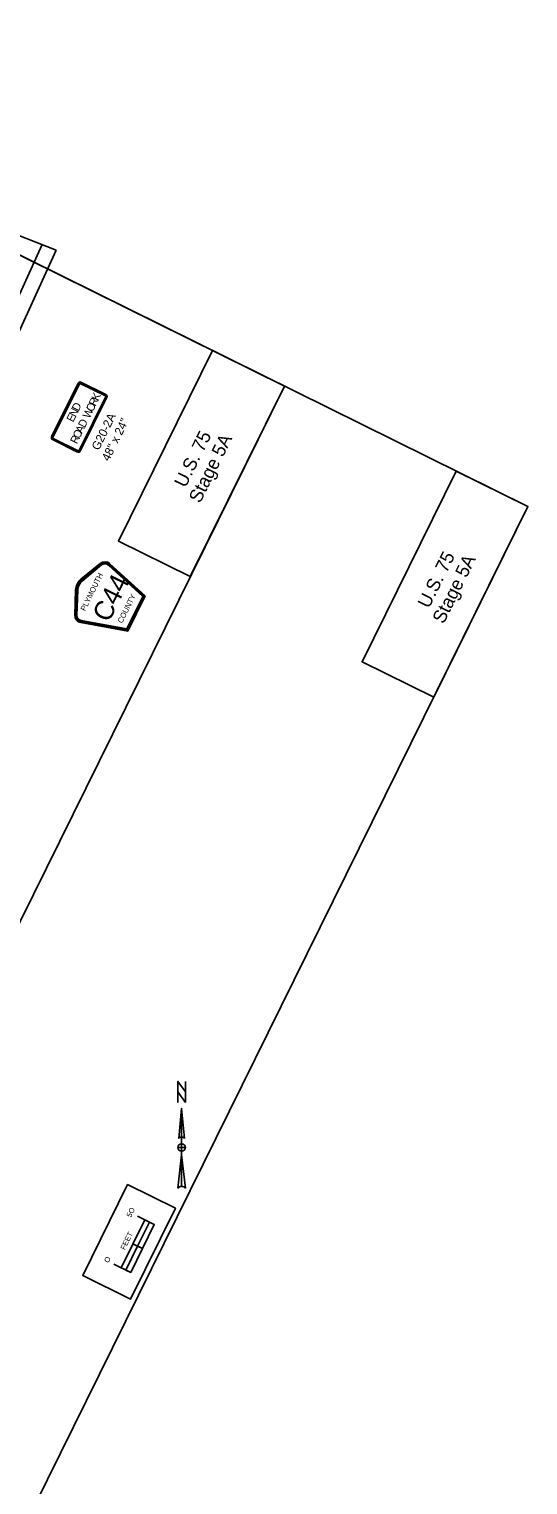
# Model space of a CAD drawing. Extents: x 14104283 to 14129344, y 8637090 to 8673339.
# Drawn here: x 14120414 to 14120882, y 8670301 to 8671666 of the extents above; entities that cross this region are included whole.
import ezdxf

# ---------------------------------------------------------------- set-up
doc = ezdxf.new("R2010")
doc.units = 0
for name, color, linetype in [('Cell', 7, 'Continuous'), ('Default', 7, 'Continuous'), ('dsnCellsNorthArrow', 7, 'Continuous'), ('dsnCellsScaleBlock', 7, 'Continuous'), ('dsnNonPlotable', 7, 'Continuous'), ('dsnPaintExistingBrokenLaneLineWhite', 7, 'Continuous'), ('dsnTextOverlapEven', 7, 'Continuous'), ('Sign', 7, 'Continuous')]:
    doc.layers.add(name, color=color, linetype=linetype)

msp = doc.modelspace()

# ---------------------------------------------------------------- linework, layer by layer
at = {"layer": 'Cell'}
for p, q in [((14120460.2, 8671333.9), (14120435.2, 8671283.5)), ((14120462.1, 8671333.6), (14120462.5, 8671334.3)), ((14120486.2, 8671323.1), (14120462.7, 8671334.7)), ((14120460.6, 8671333.7), (14120461.3, 8671333.3)), ((14120462.1, 8671270.2), (14120487, 8671320.6)), ((14120486, 8671322.7), (14120485.6, 8671322)), ((14120485.9, 8671321.2), (14120486.6, 8671320.8)), ((14120436.3, 8671282.9), (14120435.6, 8671283.3)), ((14120436.1, 8671281), (14120459.6, 8671269.3)), ((14120436.3, 8671281.4), (14120436.6, 8671282.1)), ((14120460.2, 8671270.4), (14120459.8, 8671269.7)), ((14120461.7, 8671270.4), (14120461, 8671270.7))]:
    msp.add_line(p, q, dxfattribs=at)
for points in [[(14120486, 8671322.7), (14120462.5, 8671334.3), (14120462.1, 8671333.6), (14120485.6, 8671322), (14120486, 8671322.7)], [(14120460.6, 8671333.7), (14120435.6, 8671283.3), (14120436.3, 8671282.9), (14120461.3, 8671333.3), (14120460.6, 8671333.7)], [(14120461.7, 8671270.4), (14120486.6, 8671320.8), (14120485.9, 8671321.2), (14120461, 8671270.7), (14120461.7, 8671270.4)], [(14120436.3, 8671281.4), (14120459.8, 8671269.7), (14120460.2, 8671270.4), (14120436.6, 8671282.1), (14120436.3, 8671281.4)]]:
    msp.add_lwpolyline(points, close=True, dxfattribs=at)
for centre, radius, start, end in [((14120461.8, 8671333.1), 1.87, 63.6912, 153.6914), ((14120461.8, 8671333.1), 1.41, 63.6912, 153.6914), ((14120461.8, 8671333.1), 0.625, 63.6912, 153.6914), ((14120485.4, 8671321.4), 0.625, 333.6912, 63.6914), ((14120485.4, 8671321.4), 1.41, 333.6912, 63.6914), ((14120485.4, 8671321.4), 1.87, 333.6912, 63.6914), ((14120436.9, 8671282.6), 1.87, 153.6914, 243.691), ((14120436.9, 8671282.6), 1.41, 153.6914, 243.691), ((14120436.9, 8671282.6), 0.625, 153.6914, 243.691), ((14120460.4, 8671271), 1.87, 243.691, 333.6912), ((14120460.4, 8671271), 1.41, 243.691, 333.6912), ((14120460.4, 8671271), 0.625, 243.691, 333.6912)]:
    msp.add_arc(centre, radius, start, end, dxfattribs=at)
at = {"layer": 'Default'}
for p, q in [((14120377.9, 8671482.5), (14120439.4, 8671458.6)), ((14120439.4, 8671458.6), (14120360.6, 8671285.8))]:
    msp.add_line(p, q, dxfattribs=at)
at = {"layer": 'dsnCellsNorthArrow'}
for p, q in [((14120557.2, 8670653.9), (14120560, 8670625.8)), ((14120557.2, 8670653.9), (14120557.2, 8670580.7)), ((14120554.4, 8670625.8), (14120554.4, 8670625.8)), ((14120554.5, 8670626), (14120555, 8670626.6)), ((14120557.2, 8670613.8), (14120557.2, 8670613.8)), ((14120553.7, 8670579.3), (14120557.2, 8670610.3))]:
    msp.add_line(p, q, dxfattribs=at)
msp.add_lwpolyline([(14120560.7, 8670659.6), (14120553.7, 8670669.4), (14120553.7, 8670679.3), (14120560.7, 8670669.4)], close=True, dxfattribs=at)
for points in [[(14120553.7, 8670659.6), (14120553.7, 8670679.3), (14120560.7, 8670669.4), (14120560.7, 8670679.3)], [(14120554.4, 8670625.8), (14120557.2, 8670653.9), (14120557.2, 8670627.2)], [(14120557.2, 8670613.8), (14120557.2, 8670617.3), (14120553.7, 8670617.3)], [(14120560.7, 8670617.3), (14120557.2, 8670617.3), (14120557.2, 8670620.8)], [(14120557.2, 8670580.7), (14120557.2, 8670610.3), (14120560.7, 8670579.3)]]:
    msp.add_lwpolyline(points, dxfattribs=at)
for centre, radius, start, end in [((14120557.2, 8670623.7), 3.52, 90.0204, 143.1257), ((14120557.2, 8670623.7), 3.52, 36.8481, 90.0218), ((14120557.2, 8670617.3), 3.52, 90, 180), ((14120557.2, 8670617.3), 3.52, 180, 270), ((14120557.2, 8670617.3), 3.52, 0, 90), ((14120557.2, 8670617.3), 3.52, 270, 360), ((14120557.2, 8670575.6), 5.1, 89.9894, 133.619), ((14120557.2, 8670575.6), 5.11, 46.4021, 90.0006)]:
    msp.add_arc(centre, radius, start, end, dxfattribs=at)
at = {"layer": 'dsnCellsScaleBlock'}
msp.add_line((14120520.5, 8670522.6), (14120511.5, 8670527), dxfattribs=at)
msp.add_line((14120520.5, 8670522.6), (14120511.5, 8670527), dxfattribs=at)
for points in [[(14120464.4, 8670497.3), (14120506.5, 8670582.5), (14120551.4, 8670560.3), (14120509.3, 8670475.2)], [(14120509.3, 8670475.2), (14120464.4, 8670497.3), (14120506.5, 8670582.5), (14120551.4, 8670560.3)], [(14120515.9, 8670524.8), (14120527, 8670547.3), (14120522.6, 8670549.5), (14120511.5, 8670527)], [(14120509.4, 8670500.2), (14120520.5, 8670522.6), (14120515.9, 8670524.8), (14120504.9, 8670502.4)]]:
    msp.add_lwpolyline(points, close=True, dxfattribs=at)
for points in [[(14120493.7, 8670508), (14120509.4, 8670500.2), (14120531.5, 8670545), (14120515.8, 8670552.8)], [(14120500.4, 8670504.6), (14120522.6, 8670549.5)]]:
    msp.add_lwpolyline(points, dxfattribs=at)
at = {"layer": 'dsnNonPlotable'}
for points in [[(14119282, 8670260.6), (14119976.8, 8671665.7), (14120882.2, 8671218.1), (14120187.4, 8669813)], [(14119506.2, 8670149.8), (14120200.9, 8671554.9), (14120653.6, 8671331.1), (14119958.8, 8669926)]]:
    msp.add_lwpolyline(points, close=True, dxfattribs=at)
at = {"layer": 'dsnPaintExistingBrokenLaneLineWhite'}
msp.add_line((14120347.5, 8671290.9), (14120426.4, 8671463.7), dxfattribs=at)
at = {"layer": 'dsnTextOverlapEven'}
for points in [[(14120653.6, 8671331.1), (14120565.3, 8671152.5), (14120498, 8671185.7), (14120586.3, 8671364.3)], [(14120498, 8671185.7), (14120586.3, 8671364.3), (14120653.6, 8671331.1), (14120565.3, 8671152.5)], [(14120882.2, 8671218.1), (14120793.8, 8671039.4), (14120726.6, 8671072.7), (14120814.9, 8671251.3)], [(14120726.6, 8671072.7), (14120814.9, 8671251.3), (14120882.2, 8671218.1), (14120793.8, 8671039.4)]]:
    msp.add_lwpolyline(points, close=True, dxfattribs=at)
at = {"layer": 'Sign'}
for p, q in [((14120462.7, 8671150), (14120480.8, 8671164.9)), ((14120481.4, 8671164.1), (14120463.3, 8671149.3)), ((14120463.3, 8671149.3), (14120481.4, 8671164.1)), ((14120464, 8671148.5), (14120482, 8671163.4)), ((14120482, 8671163.4), (14120464, 8671148.5)), ((14120488.6, 8671163.2), (14120520.7, 8671133.9)), ((14120520.7, 8671133.9), (14120488.6, 8671163.2)), ((14120521.9, 8671134.2), (14120489.3, 8671163.9)), ((14120489.3, 8671163.9), (14120521.9, 8671134.2)), ((14120489.9, 8671164.6), (14120523, 8671134.4)), ((14120456.9, 8671116.5), (14120457.7, 8671139.9)), ((14120458.7, 8671139.8), (14120457.8, 8671116.4)), ((14120457.8, 8671116.4), (14120458.7, 8671139.8)), ((14120458.8, 8671116.4), (14120459.7, 8671139.8)), ((14120459.7, 8671139.8), (14120458.8, 8671116.4)), ((14120520.7, 8671133.9), (14120505.7, 8671103.6)), ((14120505.7, 8671103.6), (14120520.7, 8671133.9)), ((14120506.2, 8671102.5), (14120521.9, 8671134.2)), ((14120521.9, 8671134.2), (14120506.2, 8671102.5)), ((14120523, 8671134.4), (14120506.7, 8671101.4)), ((14120523, 8671134.4), (14120521.9, 8671134.2)), ((14120506.7, 8671101.4), (14120462.6, 8671109.4)), ((14120462.8, 8671110.3), (14120506.2, 8671102.5)), ((14120506.2, 8671102.5), (14120462.8, 8671110.3)), ((14120505.7, 8671103.6), (14120462.9, 8671111.3)), ((14120462.9, 8671111.3), (14120505.7, 8671103.6)), ((14120505.7, 8671103.6), (14120506.2, 8671102.5))]:
    msp.add_line(p, q, dxfattribs=at)
for centre, radius, start, end in [((14120485.2, 8671159.5), 6.97, 47.5883, 129.4611), ((14120485.2, 8671159.5), 5.99, 47.5883, 129.4611), ((14120485.2, 8671159.5), 5.99, 47.5883, 129.4611), ((14120485.2, 8671159.5), 5.02, 47.5883, 129.4611), ((14120485.2, 8671159.5), 5.02, 47.5883, 129.4611), ((14120471.5, 8671139.4), 13.8, 129.4611, 177.9213), ((14120471.5, 8671139.4), 12.8, 129.4611, 177.9213), ((14120471.5, 8671139.4), 12.8, 129.4611, 177.9213), ((14120471.5, 8671139.4), 11.8, 129.4611, 177.9213), ((14120471.5, 8671139.4), 11.8, 129.4611, 177.9213), ((14120463.8, 8671116.2), 6.97, 177.9213, 259.7941), ((14120463.8, 8671116.2), 5.99, 177.9213, 259.7941), ((14120463.8, 8671116.2), 5.99, 177.9213, 259.7941), ((14120463.8, 8671116.2), 5.02, 177.9213, 259.7941), ((14120463.8, 8671116.2), 5.02, 177.9213, 259.7941)]:
    msp.add_arc(centre, radius, start, end, dxfattribs=at)

# ---------------------------------------------------------------- texts
at = {"layer": 'Cell'}
for s, height, p in [('R', 7.5, (14120476.3, 8671311.6)), ('K', 7.5, (14120478.8, 8671316.6)), ('N', 7.5, (14120457.7, 8671301.5)), ('D', 7.5, (14120460.4, 8671306.9)), ('W', 7.5, (14120470.6, 8671300.1)), ('O', 7.5, (14120473.7, 8671306.3)), ('E', 7.5, (14120455.4, 8671296.7)), ('A', 7.5, (14120463.7, 8671286.1)), ('D', 7.5, (14120466.3, 8671291.4)), ('G20-2A', 8, (14120479.4, 8671270.2)), ('48" x 24"', 8, (14120488.9, 8671260.1)), ('R', 7.5, (14120458.9, 8671276.3)), ('O', 7.5, (14120461.2, 8671281.1))]:
    msp.add_text(s, height=height, rotation=63.6912, dxfattribs=at).set_placement(p)
at = {"layer": 'dsnCellsScaleBlock'}
for s, p in [('5O', (14120509.6, 8670551.3)), ('FEET', (14120503.9, 8670520.8)), ('O', (14120488.5, 8670508.7))]:
    msp.add_text(s, height=5, rotation=63.6912, dxfattribs=at).set_placement(p)
at = {"layer": 'dsnTextOverlapEven'}
for s, p in [('U.S. 75', (14120560.8, 8671235.1)), ('Stage 5A', (14120574.5, 8671220.6)), ('U.S. 75', (14120789.3, 8671122)), ('Stage 5A', (14120803.1, 8671107.5))]:
    msp.add_text(s, height=12.5, rotation=63.6912, dxfattribs=at).set_placement(p)
at = {"layer": 'Sign'}
for s, height, p in [('PLYMOUTH', 5.18, (14120466.6, 8671119.8)), ('C44', 18.14, (14120488.9, 8671108.7)), ('COUNTY', 5.18, (14120501.4, 8671108.3))]:
    msp.add_text(s, height=height, rotation=63.6912, dxfattribs=at).set_placement(p)

doc.saveas('drawing.dxf')
